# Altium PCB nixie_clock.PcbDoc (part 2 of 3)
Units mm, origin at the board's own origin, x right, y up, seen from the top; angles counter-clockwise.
Board outline 295 x 120 mm, 2 copper layers (Top Layer, Bottom Layer), stack 0.325 mm thick; 320 components, 396 nets, 1330 pads, 452 vias.
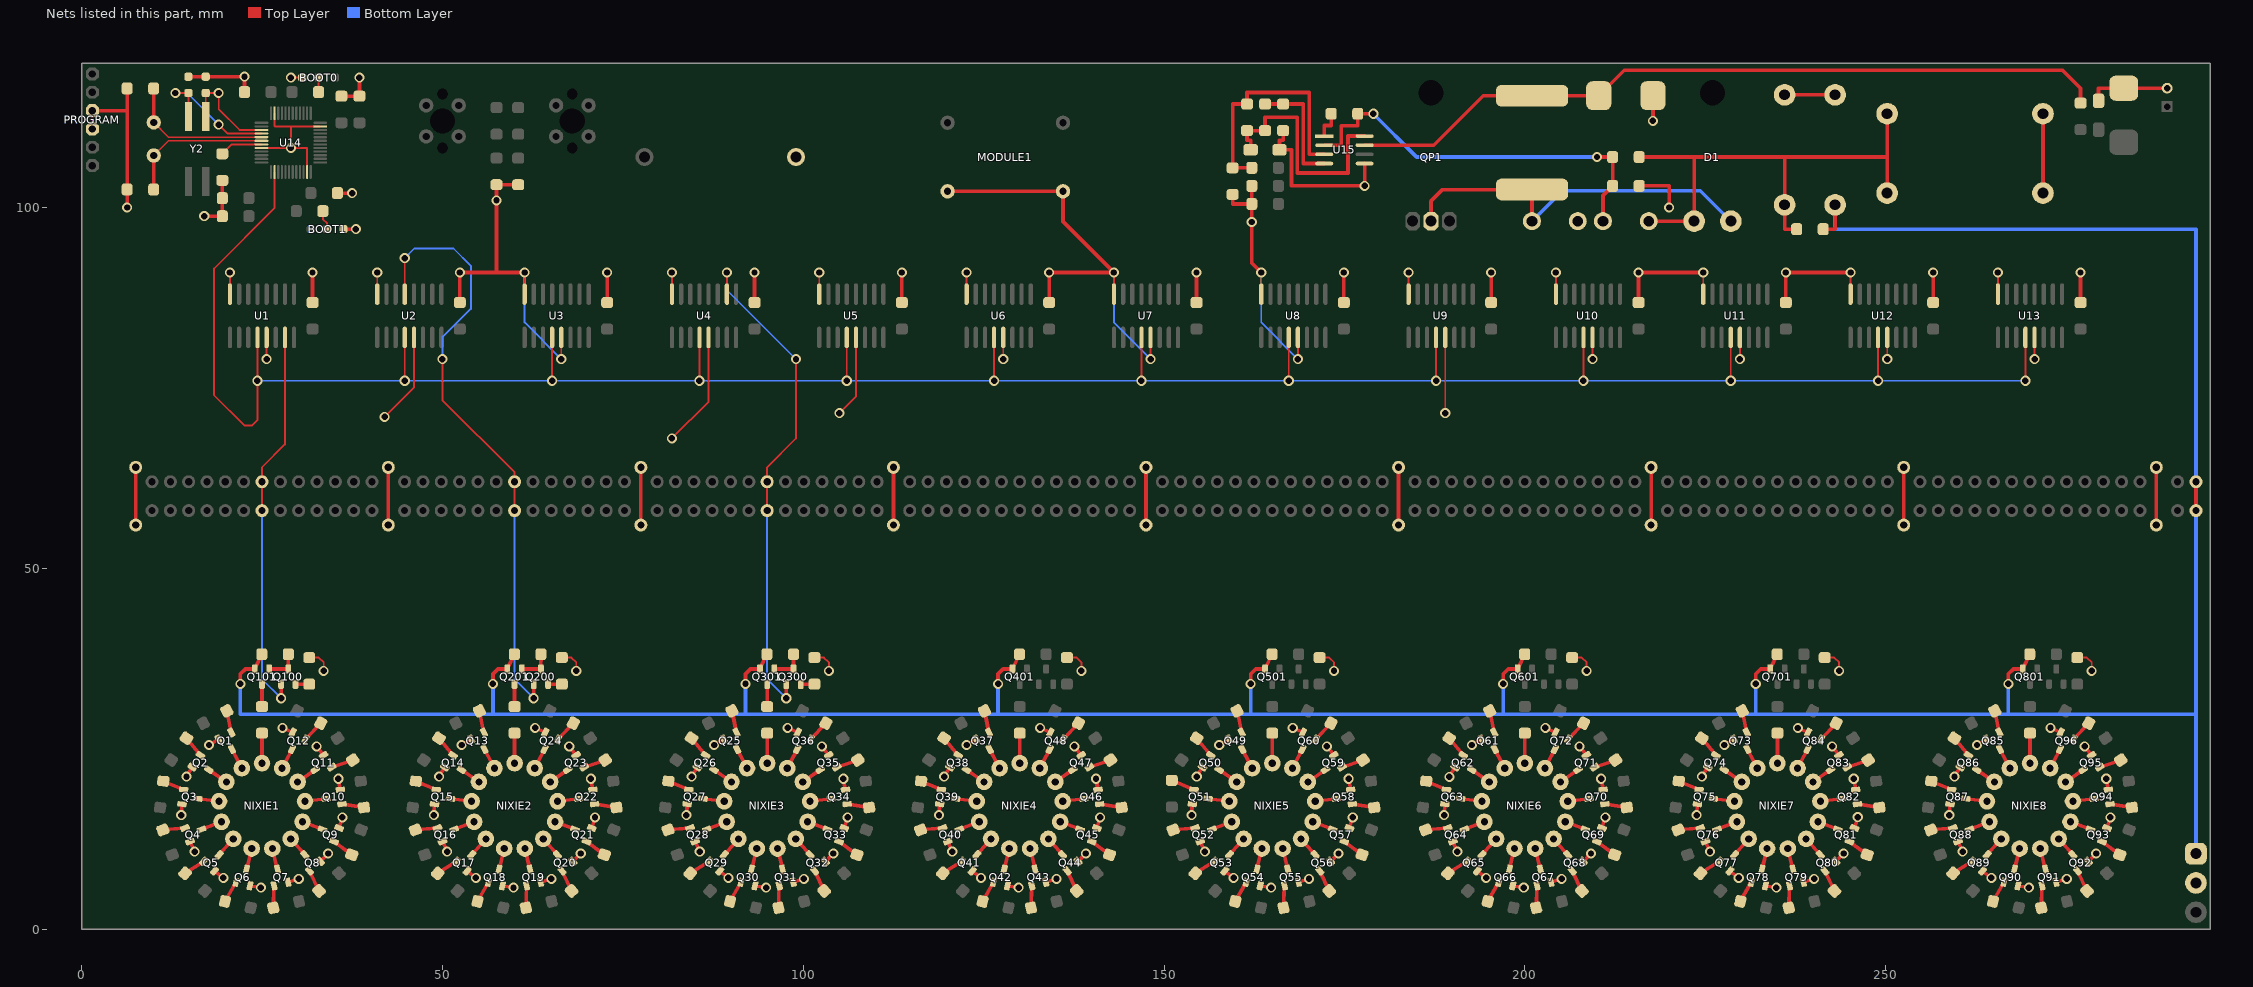
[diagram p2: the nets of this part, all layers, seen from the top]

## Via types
v1: diameter 1.397, hole 0.889, Top Layer to Bottom Layer, 452 vias

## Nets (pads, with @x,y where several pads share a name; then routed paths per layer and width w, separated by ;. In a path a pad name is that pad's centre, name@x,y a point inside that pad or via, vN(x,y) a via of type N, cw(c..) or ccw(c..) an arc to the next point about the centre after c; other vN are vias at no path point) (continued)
GND: BOOT0.3 BOOT1.3 C1.1 C2.1 C3.1 C4.1 C5.1 C6.1 C7.1 C8.1 C9.1 C10.1 C11.1 C12.1 C13.1 C14.1 C15.1 C16.1 C17.1 C18.1 C19.1 C20.1 C21.1 C22.1 C23.1 C24.1 CoinCell.1 CP1.2 CP2.2 CP3.2 CP7.2 CP9.2 CP10.2 CP11.2 CP12.2 CP15.2 CP16.2 CP18.2 MODULE1.1 MODULE1.4 P1.2 pad.802 pad.807 pad.808 pad.809 pad.810 pad.811 pad.812 pad.813 pad.814 pad.815 pad.816 pad.817 pad.818 pad.819 pad.820 pad.825 pad.826 pad.827 pad.828 PROGRAM.3 PROGRAM.4 Q1.2 Q2.2 Q3.2 Q4.2 Q5.2 Q6.2 Q7.2 Q8.2 Q9.2 Q10.2 Q11.2 Q12.2 Q13.2 Q14.2 Q15.2 Q16.2 Q17.2 Q18.2 Q19.2 Q20.2 Q21.2 Q22.2 Q23.2 Q24.2 Q25.2 Q26.2 Q27.2 Q28.2 Q29.2 Q30.2 Q31.2 Q32.2 Q33.2 Q34.2 Q35.2 Q36.2 Q37.2 Q38.2 Q39.2 Q40.2 Q41.2 Q42.2 Q43.2 Q44.2 Q45.2 Q46.2 Q47.2 Q48.2 Q49.2 Q50.2 Q51.2 Q52.2 Q53.2 Q54.2 Q55.2 Q56.2 Q57.2 Q58.2 Q59.2 Q60.2 Q61.2 Q62.2 Q63.2 Q64.2 Q65.2 Q66.2 Q67.2 Q68.2 Q69.2 Q70.2 Q71.2 Q72.2 Q73.2 Q74.2 Q75.2 Q76.2 Q77.2 Q78.2 Q79.2 Q80.2 Q81.2 Q82.2 Q83.2 Q84.2 Q85.2 Q86.2 Q87.2 Q88.2 Q89.2 Q90.2 Q91.2 Q92.2 Q93.2 Q94.2 Q95.2 Q96.2 R100.2 R111.1 R112.1 R200.2 R300.2 R400.2 R500.2 R600.2 R700.2 R800.2 RP10.2 RP11.2 RP16.2 U1.8 U1.13 U2.8 U2.13 U3.8 U3.13 U4.8 U4.13 U5.8 U5.13 U6.8 U6.13 U7.8 U7.13 U8.8 U8.13 U9.8 U9.13 U10.8 U10.13 U11.8 U11.13 U12.8 U12.13 U13.8 U13.13 U14.8 U14.23 U14.35 U14.47 U15.5 | length 694.6
  Top Layer w0.254: U1.8@20.555,88 v1(20.555,91) ; U14.8@24.925,108.25 v1(29,108.25) ; v1(25.635,79) U1.13@25.635,82 ; U14.47@26.75,113.075 26.75,111.3 26.81,111.24 29,111.24 ; v1(29,118) BOOT0.3@30.58,118 ; U14.23@31.25,104.925 31.25,108.25 v1(29,108.25) ; R100.2@31.55,37.637 32.873,37.637 33.55,36.96 v1(33.55,35.795) ; U14.35@33.075,111.25 29.01,111.25 29,111.24 ; U2.8@40.972,88 v1(40.972,91) ; v1(42,71) 46.052,75.052 U2.13@46.052,82 ; U3.8@61.388,88 v1(61.388,91) ; v1(66.468,79) U3.13@66.468,82 ; R200.2@66.55,37.637 67.873,37.637 68.55,36.96 v1(68.55,35.795) ; v1(81.805,68) 86.885,73.08 U4.13@86.885,82 ; U4.8@81.805,88 v1(81.805,91) ; R300.2@101.55,37.637 102.873,37.637 103.55,36.96 v1(103.55,35.795) ; U5.8@102.222,88 v1(102.222,91) ; v1(105,71.5) 107.302,73.802 U5.13@107.302,82 ; U6.8@122.638,88 v1(122.638,91) ; v1(127.718,79) U6.13@127.718,82 ; R400.2@136.55,37.637 137.873,37.637 138.55,36.96 v1(138.55,35.795) ; U7.8@143.055,88 v1(143.055,91) ; v1(148.135,79) U7.13@148.135,82 ; U8.8@163.472,88 v1(163.472,91) ; v1(168.552,79) U8.13@168.552,82 ; R500.2@171.55,37.637 172.873,37.637 173.55,36.96 v1(173.55,35.795) ; U9.8@183.888,88 v1(183.888,91) ; v1(188.968,71.5) U9.13@188.968,82 ; U10.8@204.305,88 v1(204.305,91) ; R600.2@206.55,37.637 207.873,37.637 208.55,36.96 v1(208.55,35.795) ; v1(209.385,79) U10.13@209.385,82 ; U11.8@224.722,88 v1(224.722,91) ; v1(229.802,79) U11.13@229.802,82 ; R700.2@241.55,37.637 242.873,37.637 243.55,36.96 v1(243.55,35.795) ; U12.8@245.138,88 v1(245.138,91) ; v1(250.218,79) U12.13@250.218,82 ; U13.8@265.555,88 v1(265.555,91) ; v1(270.635,79) U13.13@270.635,82 ; R800.2@276.55,37.637 277.873,37.637 278.55,36.96 v1(278.55,35.795) ; v1(29,108.25) 29,111.24
  Top Layer w0.508: PROGRAM.4@1.49,110.89 PROGRAM.3@1.49,113.43 6.189,113.43 6.309,113.31 ; C15.1@6.309,102.5 6.309,113.31 ; C14.1@6.309,116.5 6.309,113.31 ; v1(6.309,100) C15.1@6.309,102.5 ; pad.827@7.5,56 pad.828@7.5,64 ; v1(13.815,15.794) Q3.2@13.91,17.339 ; v1(14.536,21.13) Q2.2@15.338,22.454 ; C17.1@14.8,118.13 C16.1@17.2,118.13 v1(22.569,118.13) C21.1@22.569,116 ; Q4.2@15.023,12.147 v1(15.656,10.734) ; v1(17,98.8) C23.1@19.499,98.8 C24.1@19.499,101.3 19.5,101.301 C18.1@19.5,103.759 ; v1(17.654,25.52) Q1.2@18.979,26.32 ; Q5.2@18.421,8.066 v1(19.638,7.11) ; Q6.2@23.326,6.032 v1(24.848,5.751) ; v1(27.839,27.886) Q12.2@29.25,27.249 ; Q7.2@28.615,6.51 v1(30.093,6.969) ; C1.1@32,86.842 v1(32,91) ; v1(32.573,25.32) Q11.2@33.526,24.1 ; Q8.2@33.076,9.392 v1(34.172,10.485) ; C19.1@35.441,102 v1(37.5,102) ; v1(35.572,20.848) Q10.2@35.849,19.324 ; Q9.2@35.686,14.016 v1(36.149,15.493) ; C20.1@36,115.431 C22.1@38.5,115.431 v1(38.5,118) ; BOOT1.3@36.28,97 v1(38,97) ; pad.820@42.5,56 pad.807@42.5,64 ; v1(48.815,15.794) Q15.2@48.91,17.339 ; v1(49.536,21.13) Q14.2@50.338,22.454 ; Q16.2@50.023,12.147 v1(50.656,10.734) ; C2.1@52.417,86.842 v1(52.417,91) 57.33,91 ; v1(52.654,25.52) Q13.2@53.979,26.32 ; Q17.2@53.421,8.066 v1(54.638,7.11) ; Q18.2@58.326,6.032 v1(59.848,5.751) ; R111.1@60.5,103.159 R112.1@57.5,103.159 v1(57.5,101) 57.5,91.17 57.33,91 ; v1(61.388,91) 57.33,91 ; v1(62.839,27.886) Q24.2@64.25,27.249 ; Q19.2@63.615,6.51 v1(65.093,6.969) ; v1(67.573,25.32) Q23.2@68.526,24.1 ; Q20.2@68.076,9.392 v1(69.172,10.485) ; v1(70.572,20.848) Q22.2@70.849,19.324 ; Q21.2@70.686,14.016 v1(71.149,15.493) ; C3.1@72.833,86.842 v1(72.833,91) ; pad.819@77.5,56 pad.809@77.5,64 ; v1(83.815,15.794) Q27.2@83.91,17.339 ; v1(84.536,21.13) Q26.2@85.338,22.454 ; Q28.2@85.023,12.147 v1(85.656,10.734) ; v1(87.654,25.52) Q25.2@88.979,26.32 ; Q29.2@88.421,8.066 v1(89.638,7.11) ; C4.1@93.25,86.842 v1(93.25,91) ; Q30.2@93.326,6.032 v1(94.848,5.751) ; v1(97.839,27.886) Q36.2@99.25,27.249 ; Q31.2@98.615,6.51 v1(100.093,6.969) ; v1(102.573,25.32) Q35.2@103.526,24.1 ; Q32.2@103.076,9.392 v1(104.172,10.485) ; v1(105.572,20.848) Q34.2@105.849,19.324 ; Q33.2@105.686,14.016 v1(106.149,15.493) ; pad.818@112.5,56 pad.810@112.5,64 ; C5.1@113.667,86.842 v1(113.667,91) ; v1(118.815,15.794) Q39.2@118.91,17.339 ; v1(119.536,21.13) Q38.2@120.338,22.454 ; MODULE1.4@120,102.25 MODULE1.1@136,102.25 136,98.055 v1(143.055,91) v1(134.083,91) C6.1@134.083,86.842 ; Q40.2@120.023,12.147 v1(120.656,10.734) ; v1(122.654,25.52) Q37.2@123.979,26.32 ; Q41.2@123.421,8.066 v1(124.638,7.11) ; Q42.2@128.326,6.032 v1(129.848,5.751) ; v1(132.839,27.886) Q48.2@134.25,27.249 ; Q43.2@133.615,6.51 v1(135.093,6.969) ; v1(137.573,25.32) Q47.2@138.526,24.1 ; Q44.2@138.076,9.392 v1(139.172,10.485) ; v1(140.572,20.848) Q46.2@140.849,19.324 ; Q45.2@140.686,14.016 v1(141.149,15.493) ; pad.817@147.5,56 pad.811@147.5,64 ; v1(153.815,15.794) Q51.2@153.91,17.339 ; C7.1@154.5,86.842 v1(154.5,91) ; v1(154.536,21.13) Q50.2@155.338,22.454 ; Q52.2@155.023,12.147 v1(155.656,10.734) ; v1(157.654,25.52) Q49.2@158.979,26.32 ; Q53.2@158.421,8.066 v1(159.638,7.11) ; CP11.2@159.5,101.819 159.5,100.5 RP11.2@162.159,100.5 ; RP10.2@162.159,103 RP11.2@162.159,100.5 ; Q54.2@163.326,6.032 v1(164.848,5.751) ; v1(163.472,91) 162.159,92.313 v1(162.159,98) RP11.2@162.159,100.5 ; CP7.2@166.5,110.659 166.5,109.33 166,109.33 CP10.2@166,108 167.67,108 167.67,103 v1(177.8,103) U15.5@177.8,106.095 ; v1(167.839,27.886) Q60.2@169.25,27.249 ; Q55.2@168.615,6.51 v1(170.093,6.969) ; v1(172.573,25.32) Q59.2@173.526,24.1 ; Q56.2@173.076,9.392 v1(174.172,10.485) ; C8.1@174.917,86.842 v1(174.917,91) ; v1(175.572,20.848) Q58.2@175.849,19.324 ; Q57.2@175.686,14.016 v1(176.149,15.493) ; pad.816@182.5,56 pad.812@182.5,64 ; v1(188.815,15.794) Q63.2@188.91,17.339 ; v1(189.53,21.11) Q62.2@190.338,22.454 ; Q64.2@190.023,12.147 v1(190.656,10.734) ; v1(192.654,25.52) Q61.2@193.979,26.32 ; Q65.2@193.421,8.066 v1(194.638,7.11) ; C9.1@195.333,86.842 v1(195.333,91) ; Q66.2@198.326,6.032 v1(199.848,5.751) ; v1(202.839,27.886) Q72.2@204.25,27.249 ; Q67.2@203.615,6.51 v1(205.093,6.969) ; v1(207.573,25.32) Q71.2@208.526,24.1 ; Q68.2@208.076,9.392 v1(209.172,10.485) ; v1(210.572,20.848) Q70.2@210.849,19.324 ; Q69.2@210.686,14.016 v1(211.149,15.493) ; C10.1@215.75,86.842 v1(215.75,91) v1(224.722,91) ; RP16.2@215.842,103 220,103 v1(220,100) ; pad.815@217.5,56 pad.813@217.5,64 ; v1(217.75,112) CP9.2@217.75,115.5 ; v1(223.815,15.794) Q75.2@223.91,17.339 ; v1(224.536,21.13) Q74.2@225.338,22.454 ; Q76.2@225.023,12.147 v1(225.656,10.734) ; v1(227.654,25.52) Q73.2@228.979,26.32 ; Q77.2@228.421,8.066 v1(229.638,7.11) ; Q78.2@233.326,6.032 v1(234.848,5.751) ; CP12.2@236,115.62 CP3.2@243,115.62 ; C11.1@236.167,86.842 v1(236.167,91) v1(245.138,91) ; v1(237.83,27.88) Q84.2@239.25,27.249 ; Q79.2@238.615,6.51 v1(240.093,6.969) ; v1(242.573,25.32) Q83.2@243.526,24.1 ; Q80.2@243.076,9.392 v1(244.172,10.485) ; v1(245.572,20.848) Q82.2@245.849,19.324 ; Q81.2@245.686,14.016 v1(246.13,15.52) ; pad.814@252.5,56 pad.808@252.5,64 ; C12.1@256.583,86.842 v1(256.583,91) ; v1(258.815,15.794) Q87.2@258.91,17.339 ; v1(259.536,21.13) Q86.2@260.338,22.454 ; Q88.2@260.023,12.147 v1(260.656,10.734) ; v1(262.654,25.52) Q85.2@263.979,26.32 ; Q89.2@263.421,8.066 v1(264.638,7.11) ; Q90.2@268.326,6.032 v1(269.848,5.751) ; CP2.2@271.795,102 CP1.2@271.795,113 ; v1(272.839,27.886) Q96.2@274.25,27.249 ; Q91.2@273.615,6.51 v1(275.093,6.969) ; C13.1@277,86.842 v1(277,91) ; v1(277.573,25.32) Q95.2@278.526,24.1 ; Q92.2@278.076,9.392 v1(279.172,10.485) ; CP18.2@279.5,114.79 279.5,116.54 CP16.2@283,116.54 P1.2@289,116.54 ; v1(280.572,20.848) Q94.2@280.849,19.324 ; Q93.2@280.686,14.016 v1(281.149,15.493) ; pad.825@287.5,56 pad.826@287.5,64
  Bottom Layer w0.254: v1(61.388,91) 61.388,84.08 v1(66.468,79) ; v1(143.055,91) 143.055,84.08 v1(148.135,79) ; v1(163.472,91) 163.472,84.08 v1(168.552,79)
HV: CP3.1 L2.1 pad.803 pad.823 pad.824 Q101.2 Q201.2 Q301.2 Q401.2 Q501.2 Q601.2 Q701.2 Q801.2 R102.1 R202.1 R302.1 R402.1 R502.1 R602.1 R702.1 R802.1 | length 500.9
  Top Layer w0.508: v1(22,34) 22,35.35 22.7,36.05 Q101.2@24,36.05 R102.1@24.968,38.1 ; v1(57,34) 57,35.35 57.7,36.05 Q201.2@59,36.05 R202.1@59.969,38.1 ; v1(92,34) 92,35.35 92.7,36.05 Q301.2@94,36.05 R302.1@94.968,38.1 ; v1(127,34) 127,35.35 127.7,36.05 Q401.2@129,36.05 R402.1@129.969,38.1 ; v1(162,34) 162,35.35 162.7,36.05 Q501.2@164,36.05 R502.1@164.968,38.1 ; v1(197,34) 197,35.35 197.7,36.05 Q601.2@199,36.05 R602.1@199.969,38.1 ; v1(232,34) 232,35.35 232.7,36.05 Q701.2@234,36.05 R702.1@234.968,38.1 ; L2.1@241.342,97 243,97 CP3.1@243,100.38 ; v1(267,34) 267,35.35 267.7,36.05 Q801.2@269,36.05 R802.1@269.968,38.1 ; pad.824@293,58 pad.823@293,62
  Bottom Layer w0.508: v1(22,34) 22,29.77 231.96,29.77 ; 57,29.81 v1(57,34) ; 92,29.81 v1(92,34) ; 127,29.81 v1(127,34) ; 162,29.81 v1(162,34) ; 197,29.81 v1(197,34) ; v1(232,34) 232,29.81 231.96,29.77 ; CP3.1@243,100.38 243,97.01 293,97.01 pad.823@293,62 pad.824@293,58 293,29.77 ; v1(267,34) 267,29.77 ; pad.803@293,10.47 293,29.77 ; 231.96,29.77 267,29.77 ; 267,29.77 293,29.77
LATCH: U1.12 U2.12 U3.12 U4.12 U5.12 U6.12 U7.12 U8.12 U9.12 U10.12 U11.12 U12.12 U13.12 U14.14 | length 370.9
  Top Layer w0.254: U1.12@24.365,82 v1(24.365,76) 24.365,70.525 23.65,69.81 22.55,69.81 18.35,74.01 18.35,91.54 26.75,99.94 U14.14@26.75,104.925 ; v1(44.782,76) U2.12@44.782,82 ; v1(65.198,76) U3.12@65.198,82 ; v1(85.615,76) U4.12@85.615,82 ; v1(106.032,76) U5.12@106.032,82 ; v1(126.448,76) U6.12@126.448,82 ; v1(146.865,76) U7.12@146.865,82 ; v1(167.282,76) U8.12@167.282,82 ; v1(187.698,76) U9.12@187.698,82 ; v1(208.115,76) U10.12@208.115,82 ; v1(228.532,76) U11.12@228.532,82 ; v1(248.948,76) U12.12@248.948,82 ; v1(269.365,76) U13.12@269.365,82
  Bottom Layer w0.254: v1(24.365,76) v1(44.782,76) v1(65.198,76) v1(85.615,76) v1(106.032,76) v1(126.448,76) v1(146.865,76) v1(167.282,76) v1(187.698,76) v1(208.115,76) v1(228.532,76) v1(248.948,76) v1(269.365,76)
NetBOOT0_2: BOOT0.2 R109.1 | length 2
  Top Layer w0.254: BOOT0.2@32.84,118 32.841,117.999 R109.1@32.841,116
NetBOOT1_2: BOOT1.2 R110.2 | length 2.7
  Top Layer w0.254: R110.2@33.432,99.5 33.432,98.399 34.02,97.81 BOOT1.2@34.02,97
NetC14_2: C14.2 U14.5 Y1.2 | length 20.5
  Top Layer w0.254: C14.2@9.991,116.5 C14.2@10,116.491 ; Y1.2@10,111.793 12.043,109.75 U14.5@24.925,109.75
  Top Layer w0.508: Y1.2@10,111.793 C14.2@10,116.491
NetC15_2: C15.2 U14.6 Y1.1 | length 20.5
  Top Layer w0.254: C15.2@9.991,102.5 C15.2@10,102.509 ; Y1.1@10,107.207 12.043,109.25 U14.6@24.925,109.25
  Top Layer w0.508: C15.2@10,102.509 Y1.1@10,107.207
NetC16_2: C16.2 U14.3 Y2.1 | length 14.4
  Top Layer w0.254: Y2.1@17.2,112.62 C16.2@17.2,115.87 v1(19,115.87) 19,113.63 21.88,110.75 U14.3@24.925,110.75
NetC17_2: C17.2 U14.4 Y2.2 | length 19.3
  Top Layer w0.254: v1(13,115.87) C17.2@14.8,115.87 Y2.2@14.8,112.62 ; v1(19,111.5) 20.25,110.25 U14.4@24.925,110.25
  Bottom Layer w0.254: v1(13,115.87) 14.63,115.87 v1(19,111.5)
NetC18_2: C18.2 U14.7 | length 6
  Top Layer w0.254: C18.2@19.5,107.441 20.809,108.75 U14.7@24.925,108.75
NetCP1_1: CP1.1 CP2.1 CP6.1 CP12.1 D1.2 L2.2 RP15.1 | length 72.3
  Top Layer w0.508: RP15.1@215.842,107 223.46,107 ; CP6.1@217.175,98.11 D1.2@223.46,98.11 223.46,107 ; L2.2@237.659,97 236,97 CP12.1@236,100.38 236,106.85 235.85,107 ; CP2.1@250.205,102 250.205,107.16 ; CP1.1@250.205,113 250.205,107.16 ; 223.46,107 235.85,107 ; 235.85,107 250.045,107 250.205,107.16
NetCP5_1: CP5.1 U15.1 | length 4.1
  Top Layer w0.508: U15.1@172.2,109.905 172.2,111.37 173.159,111.37 CP5.1@173.159,113
NetCP5_2: CP5.2 CP6.2 RP15.2 RP16.1 U15.2 | length 56.3
  Top Layer w0.508: U15.2@172.2,108.635 174.55,108.635 174.55,111.34 176.842,111.34 CP5.2@176.842,113 v1(179,113) ; v1(210,107) RP15.2@212.159,107 RP16.1@212.159,103 210.825,101.666 CP6.2@210.825,98.11
  Bottom Layer w0.508: v1(179,113) 185,107 v1(210,107)
NetCP7_1: CP7.1 RP2.2 U15.4 | length 16.4
  Top Layer w0.508: RP2.2@164,114.342 CP7.1@166.5,114.342 169.29,114.342 169.29,106.095 U15.4@172.2,106.095
NetCP9_1: CP9.1 L1.1 L3.2 U15.7 | length 106.6
  Top Layer w0.508: U15.7@177.8,108.635 187.375,108.635 194.24,115.5 L3.2@201,115.5 CP9.1@210.25,115.5 213.77,119.02 274.5,119.02 277,116.52 L1.1@277,114.472
NetCP10_1: CP10.1 RP2.1 RP12.1 U15.8 | length 34.1
  Top Layer w0.508: CP10.1@162,108 162,109.31 161.5,109.31 RP12.1@161.5,110.659 RP2.1@164,110.659 164,112.5 168.45,112.5 168.45,104.78 175.5,104.78 175.5,109.905 U15.8@177.8,109.905
NetCP11_1: CP11.1 RP8.1 RP12.2 U15.3 | length 34.4
  Top Layer w0.508: RP8.1@162.159,105.5 159.502,105.5 CP11.1@159.5,105.502 159.5,114.342 RP12.2@161.5,114.342 161.5,115.94 170.13,115.94 170.13,107.365 U15.3@172.2,107.365
NetCP15_1: CP15.1 D1.1 L3.1 QP1.2 | length 52.9
  Top Layer w0.508: QP1.2@187,98.11 187,100.89 188.595,102.485 200.985,102.485 CP15.1@200.985,98.11
  Bottom Layer w0.508: CP15.1@200.985,98.11 205.215,102.34 224.31,102.34 D1.1@228.54,98.11
NetNIXIE1_0: NIXIE1.0 Q11.3 | length 3
  Top Layer w0.508: NIXIE1.0@29.938,20.408 Q11.3@32.366,22.084
NetNIXIE1_1: NIXIE1.1 Q2.3 | length 3
  Top Layer w0.508: Q2.3@17.634,22.084 NIXIE1.1@20.062,20.408
NetNIXIE1_2: NIXIE1.2 Q3.3 | length 3
  Top Layer w0.508: Q3.3@16.115,18.079 NIXIE1.2@19.044,17.723
NetNIXIE1_3: NIXIE1.3 Q4.3 | length 3
  Top Layer w0.508: Q4.3@16.632,13.826 NIXIE1.3@19.39,14.872
NetNIXIE1_4: NIXIE1.4 Q5.3 | length 3
  Top Layer w0.508: Q5.3@19.065,10.301 NIXIE1.4@21.021,12.509
NetNIXIE1_5: NIXIE1.5 Q6.3 | length 3
  Top Layer w0.508: Q6.3@22.858,8.31 NIXIE1.5@23.564,11.174
NetNIXIE1_6: NIXIE1.6 Q7.3 | length 3
  Top Layer w0.508: NIXIE1.6@26.436,11.174 Q7.3@27.142,8.31
NetNIXIE1_7: NIXIE1.7 Q8.3 | length 3
  Top Layer w0.508: NIXIE1.7@28.979,12.509 Q8.3@30.935,10.301
NetNIXIE1_8: NIXIE1.8 Q9.3 | length 3
  Top Layer w0.508: NIXIE1.8@30.61,14.872 Q9.3@33.368,13.826
NetNIXIE1_9: NIXIE1.9 Q10.3 | length 3
  Top Layer w0.508: NIXIE1.9@30.956,17.723 Q10.3@33.885,18.078
NetNIXIE1_A: NIXIE1.A R101.2 | length 4.2
  Top Layer w0.508: NIXIE1.A@25,23 R101.2@25,27.159
NetNIXIE1_LP: NIXIE1.LP Q1.3 | length 3
  Top Layer w0.508: Q1.3@20.841,24.925 NIXIE1.LP@22.212,22.313
NetNIXIE1_RP: NIXIE1.RP Q12.3 | length 3
  Top Layer w0.508: NIXIE1.RP@27.789,22.313 Q12.3@29.16,24.925
NetNIXIE2_0: NIXIE2.0 Q23.3 | length 2.9
  Top Layer w0.508: NIXIE2.0@64.938,20.408 Q23.3@67.366,22.084
NetNIXIE2_1: NIXIE2.1 Q14.3 | length 3
  Top Layer w0.508: Q14.3@52.634,22.084 NIXIE2.1@55.062,20.408
NetNIXIE2_2: NIXIE2.2 Q15.3 | length 2.9
  Top Layer w0.508: Q15.3@51.115,18.079 NIXIE2.2@54.044,17.723
NetNIXIE2_3: NIXIE2.3 Q16.3 | length 3
  Top Layer w0.508: Q16.3@51.632,13.826 NIXIE2.3@54.39,14.872
NetNIXIE2_4: NIXIE2.4 Q17.3 | length 3
  Top Layer w0.508: Q17.3@54.065,10.301 NIXIE2.4@56.021,12.509
NetNIXIE2_5: NIXIE2.5 Q18.3 | length 3
  Top Layer w0.508: Q18.3@57.858,8.31 NIXIE2.5@58.564,11.174
NetNIXIE2_6: NIXIE2.6 Q19.3 | length 3
  Top Layer w0.508: NIXIE2.6@61.436,11.174 Q19.3@62.142,8.31
NetNIXIE2_7: NIXIE2.7 Q20.3 | length 3
  Top Layer w0.508: NIXIE2.7@63.979,12.509 Q20.3@65.935,10.301
NetNIXIE2_8: NIXIE2.8 Q21.3 | length 3
  Top Layer w0.508: NIXIE2.8@65.61,14.872 Q21.3@68.368,13.826
NetNIXIE2_9: NIXIE2.9 Q22.3 | length 3
  Top Layer w0.508: NIXIE2.9@65.956,17.723 Q22.3@68.885,18.078
NetNIXIE2_A: NIXIE2.A R201.2 | length 4.2
  Top Layer w0.508: NIXIE2.A@60,23 R201.2@60,27.159
NetNIXIE2_LP: NIXIE2.LP Q13.3 | length 2.9
  Top Layer w0.508: Q13.3@55.841,24.925 NIXIE2.LP@57.212,22.313
NetNIXIE2_RP: NIXIE2.RP Q24.3 | length 2.9
  Top Layer w0.508: NIXIE2.RP@62.789,22.313 Q24.3@64.16,24.925
NetNIXIE3_0: NIXIE3.0 Q35.3 | length 3
  Top Layer w0.508: NIXIE3.0@99.938,20.408 Q35.3@102.366,22.084
NetNIXIE3_1: NIXIE3.1 Q26.3 | length 3
  Top Layer w0.508: Q26.3@87.634,22.084 NIXIE3.1@90.062,20.408
NetNIXIE3_2: NIXIE3.2 Q27.3 | length 3
  Top Layer w0.508: Q27.3@86.115,18.079 NIXIE3.2@89.044,17.723
NetNIXIE3_3: NIXIE3.3 Q28.3 | length 3
  Top Layer w0.508: Q28.3@86.632,13.826 NIXIE3.3@89.39,14.872
NetNIXIE3_4: NIXIE3.4 Q29.3 | length 3
  Top Layer w0.508: Q29.3@89.065,10.301 NIXIE3.4@91.021,12.509
NetNIXIE3_5: NIXIE3.5 Q30.3 | length 3
  Top Layer w0.508: Q30.3@92.858,8.31 NIXIE3.5@93.564,11.174
NetNIXIE3_6: NIXIE3.6 Q31.3 | length 3
  Top Layer w0.508: NIXIE3.6@96.436,11.174 Q31.3@97.142,8.31
NetNIXIE3_7: NIXIE3.7 Q32.3 | length 3
  Top Layer w0.508: NIXIE3.7@98.979,12.509 Q32.3@100.935,10.301
NetNIXIE3_8: NIXIE3.8 Q33.3 | length 3
  Top Layer w0.508: NIXIE3.8@100.61,14.872 Q33.3@103.368,13.826
NetNIXIE3_9: NIXIE3.9 Q34.3 | length 3
  Top Layer w0.508: NIXIE3.9@100.956,17.723 Q34.3@103.885,18.078
NetNIXIE3_A: NIXIE3.A R301.2 | length 4.2
  Top Layer w0.508: NIXIE3.A@95,23 R301.2@95,27.159
NetNIXIE3_LP: NIXIE3.LP Q25.3 | length 3
  Top Layer w0.508: Q25.3@90.841,24.925 NIXIE3.LP@92.212,22.313
NetNIXIE3_RP: NIXIE3.RP Q36.3 | length 3
  Top Layer w0.508: NIXIE3.RP@97.789,22.313 Q36.3@99.16,24.925
NetNIXIE4_0: NIXIE4.0 Q47.3 | length 3
  Top Layer w0.508: NIXIE4.0@134.938,20.408 Q47.3@137.366,22.084
NetNIXIE4_1: NIXIE4.1 Q38.3 | length 3
  Top Layer w0.508: Q38.3@122.634,22.084 NIXIE4.1@125.062,20.408
NetNIXIE4_2: NIXIE4.2 Q39.3 | length 3
  Top Layer w0.508: Q39.3@121.115,18.079 NIXIE4.2@124.044,17.723
NetNIXIE4_3: NIXIE4.3 Q40.3 | length 3
  Top Layer w0.508: Q40.3@121.632,13.826 NIXIE4.3@124.39,14.872
NetNIXIE4_4: NIXIE4.4 Q41.3 | length 3
  Top Layer w0.508: Q41.3@124.065,10.301 NIXIE4.4@126.021,12.509
NetNIXIE4_5: NIXIE4.5 Q42.3 | length 2.9
  Top Layer w0.508: Q42.3@127.858,8.31 NIXIE4.5@128.564,11.174
NetNIXIE4_6: NIXIE4.6 Q43.3 | length 3
  Top Layer w0.508: NIXIE4.6@131.436,11.174 Q43.3@132.142,8.31
NetNIXIE4_7: NIXIE4.7 Q44.3 | length 3
  Top Layer w0.508: NIXIE4.7@133.979,12.509 Q44.3@135.935,10.301
NetNIXIE4_8: NIXIE4.8 Q45.3 | length 3
  Top Layer w0.508: NIXIE4.8@135.61,14.872 Q45.3@138.368,13.826
NetNIXIE4_9: NIXIE4.9 Q46.3 | length 3
  Top Layer w0.508: NIXIE4.9@135.956,17.723 Q46.3@138.885,18.078
NetNIXIE4_A: NIXIE4.A R401.2 | length 4.2
  Top Layer w0.508: NIXIE4.A@130,23 R401.2@130,27.159
NetNIXIE4_LP: NIXIE4.LP Q37.3 | length 3
  Top Layer w0.508: Q37.3@125.841,24.925 NIXIE4.LP@127.212,22.313
NetNIXIE4_RP: NIXIE4.RP Q48.3 | length 3
  Top Layer w0.508: NIXIE4.RP@132.789,22.313 Q48.3@134.16,24.925
NetNIXIE5_0: NIXIE5.0 Q59.3 | length 3
  Top Layer w0.508: NIXIE5.0@169.938,20.408 Q59.3@172.366,22.084
NetNIXIE5_1: NIXIE5.1 Q50.3 | length 3
  Top Layer w0.508: Q50.3@157.634,22.084 NIXIE5.1@160.062,20.408
NetNIXIE5_2: NIXIE5.2 Q51.3 | length 3
  Top Layer w0.508: Q51.3@156.115,18.079 NIXIE5.2@159.044,17.723
NetNIXIE5_3: NIXIE5.3 Q52.3 | length 3
  Top Layer w0.508: Q52.3@156.632,13.826 NIXIE5.3@159.39,14.872
NetNIXIE5_4: NIXIE5.4 Q53.3 | length 3
  Top Layer w0.508: Q53.3@159.065,10.301 NIXIE5.4@161.021,12.509
NetNIXIE5_5: NIXIE5.5 Q54.3 | length 3
  Top Layer w0.508: Q54.3@162.858,8.31 NIXIE5.5@163.564,11.174
NetNIXIE5_6: NIXIE5.6 Q55.3 | length 3
  Top Layer w0.508: NIXIE5.6@166.436,11.174 Q55.3@167.142,8.31
NetNIXIE5_7: NIXIE5.7 Q56.3 | length 3
  Top Layer w0.508: NIXIE5.7@168.979,12.509 Q56.3@170.935,10.301
NetNIXIE5_8: NIXIE5.8 Q57.3 | length 3
  Top Layer w0.508: NIXIE5.8@170.61,14.872 Q57.3@173.368,13.826
NetNIXIE5_9: NIXIE5.9 Q58.3 | length 3
  Top Layer w0.508: NIXIE5.9@170.956,17.723 Q58.3@173.885,18.078
NetNIXIE5_A: NIXIE5.A R501.2 | length 4.2
  Top Layer w0.508: NIXIE5.A@165,23 R501.2@165,27.159
NetNIXIE5_LP: NIXIE5.LP Q49.3 | length 3
  Top Layer w0.508: Q49.3@160.841,24.925 NIXIE5.LP@162.212,22.313
NetNIXIE5_RP: NIXIE5.RP Q60.3 | length 3
  Top Layer w0.508: NIXIE5.RP@167.789,22.313 Q60.3@169.16,24.925
NetNIXIE6_0: NIXIE6.0 Q71.3 | length 2.9
  Top Layer w0.508: NIXIE6.0@204.938,20.408 Q71.3@207.366,22.084
NetNIXIE6_1: NIXIE6.1 Q62.3 | length 3
  Top Layer w0.508: Q62.3@192.634,22.084 NIXIE6.1@195.062,20.408
NetNIXIE6_2: NIXIE6.2 Q63.3 | length 3
  Top Layer w0.508: Q63.3@191.115,18.079 NIXIE6.2@194.044,17.723
NetNIXIE6_3: NIXIE6.3 Q64.3 | length 3
  Top Layer w0.508: Q64.3@191.632,13.826 NIXIE6.3@194.39,14.872
NetNIXIE6_4: NIXIE6.4 Q65.3 | length 3
  Top Layer w0.508: Q65.3@194.065,10.301 NIXIE6.4@196.021,12.509
NetNIXIE6_5: NIXIE6.5 Q66.3 | length 3
  Top Layer w0.508: Q66.3@197.858,8.31 NIXIE6.5@198.564,11.174
NetNIXIE6_6: NIXIE6.6 Q67.3 | length 3
  Top Layer w0.508: NIXIE6.6@201.436,11.174 Q67.3@202.142,8.31
NetNIXIE6_7: NIXIE6.7 Q68.3 | length 3
  Top Layer w0.508: NIXIE6.7@203.979,12.509 Q68.3@205.935,10.301
NetNIXIE6_8: NIXIE6.8 Q69.3 | length 3
  Top Layer w0.508: NIXIE6.8@205.61,14.872 Q69.3@208.368,13.826
NetNIXIE6_9: NIXIE6.9 Q70.3 | length 3
  Top Layer w0.508: NIXIE6.9@205.956,17.723 Q70.3@208.885,18.078
NetNIXIE6_A: NIXIE6.A R601.2 | length 4.2
  Top Layer w0.508: NIXIE6.A@200,23 R601.2@200,27.159
NetNIXIE6_LP: NIXIE6.LP Q61.3 | length 3
  Top Layer w0.508: Q61.3@195.841,24.925 NIXIE6.LP@197.212,22.313
NetNIXIE6_RP: NIXIE6.RP Q72.3 | length 3
  Top Layer w0.508: NIXIE6.RP@202.789,22.313 Q72.3@204.16,24.925
NetNIXIE7_0: NIXIE7.0 Q83.3 | length 3
  Top Layer w0.508: NIXIE7.0@239.938,20.408 Q83.3@242.366,22.084
NetNIXIE7_1: NIXIE7.1 Q74.3 | length 3
  Top Layer w0.508: Q74.3@227.634,22.084 NIXIE7.1@230.062,20.408
NetNIXIE7_2: NIXIE7.2 Q75.3 | length 3
  Top Layer w0.508: Q75.3@226.115,18.079 NIXIE7.2@229.044,17.723
NetNIXIE7_3: NIXIE7.3 Q76.3 | length 3
  Top Layer w0.508: Q76.3@226.632,13.826 NIXIE7.3@229.39,14.872
NetNIXIE7_4: NIXIE7.4 Q77.3 | length 3
  Top Layer w0.508: Q77.3@229.065,10.301 NIXIE7.4@231.021,12.509
NetNIXIE7_5: NIXIE7.5 Q78.3 | length 3
  Top Layer w0.508: Q78.3@232.858,8.31 NIXIE7.5@233.564,11.174
NetNIXIE7_6: NIXIE7.6 Q79.3 | length 3
  Top Layer w0.508: NIXIE7.6@236.436,11.174 Q79.3@237.142,8.31
NetNIXIE7_7: NIXIE7.7 Q80.3 | length 3
  Top Layer w0.508: NIXIE7.7@238.979,12.509 Q80.3@240.935,10.301
NetNIXIE7_8: NIXIE7.8 Q81.3 | length 3
  Top Layer w0.508: NIXIE7.8@240.61,14.872 Q81.3@243.368,13.826
NetNIXIE7_9: NIXIE7.9 Q82.3 | length 3
  Top Layer w0.508: NIXIE7.9@240.956,17.723 Q82.3@243.885,18.078
NetNIXIE7_A: NIXIE7.A R701.2 | length 4.2
  Top Layer w0.508: NIXIE7.A@235,23 R701.2@235,27.159
NetNIXIE7_LP: NIXIE7.LP Q73.3 | length 3
  Top Layer w0.508: Q73.3@230.841,24.925 NIXIE7.LP@232.212,22.313
NetNIXIE7_RP: NIXIE7.RP Q84.3 | length 2.9
  Top Layer w0.508: NIXIE7.RP@237.789,22.313 Q84.3@239.16,24.925
NetNIXIE8_0: NIXIE8.0 Q95.3 | length 3
  Top Layer w0.508: NIXIE8.0@274.938,20.408 Q95.3@277.366,22.084
NetNIXIE8_1: NIXIE8.1 Q86.3 | length 3
  Top Layer w0.508: Q86.3@262.634,22.084 NIXIE8.1@265.062,20.408
NetNIXIE8_2: NIXIE8.2 Q87.3 | length 3
  Top Layer w0.508: Q87.3@261.115,18.079 NIXIE8.2@264.044,17.723
NetNIXIE8_3: NIXIE8.3 Q88.3 | length 3
  Top Layer w0.508: Q88.3@261.632,13.826 NIXIE8.3@264.39,14.872
NetNIXIE8_4: NIXIE8.4 Q89.3 | length 3
  Top Layer w0.508: Q89.3@264.065,10.301 NIXIE8.4@266.021,12.509
NetNIXIE8_5: NIXIE8.5 Q90.3 | length 3
  Top Layer w0.508: Q90.3@267.858,8.31 NIXIE8.5@268.564,11.174
NetNIXIE8_6: NIXIE8.6 Q91.3 | length 3
  Top Layer w0.508: NIXIE8.6@271.436,11.174 Q91.3@272.142,8.31
NetNIXIE8_7: NIXIE8.7 Q92.3 | length 3
  Top Layer w0.508: NIXIE8.7@273.979,12.509 Q92.3@275.935,10.301
NetNIXIE8_8: NIXIE8.8 Q93.3 | length 3
  Top Layer w0.508: NIXIE8.8@275.61,14.872 Q93.3@278.368,13.826
NetNIXIE8_9: NIXIE8.9 Q94.3 | length 3
  Top Layer w0.508: NIXIE8.9@275.956,17.723 Q94.3@278.885,18.078
NetNIXIE8_A: NIXIE8.A R801.2 | length 4.2
  Top Layer w0.508: NIXIE8.A@270,23 R801.2@270,27.159
NetNIXIE8_LP: NIXIE8.LP Q85.3 | length 3
  Top Layer w0.508: Q85.3@265.841,24.925 NIXIE8.LP@267.212,22.313
NetNIXIE8_RP: NIXIE8.RP Q96.3 | length 3
  Top Layer w0.508: NIXIE8.RP@272.789,22.313 Q96.3@274.16,24.925
NetQ1_1: Q1.1 R1.1 | length 3.1
  Top Layer w0.508: R1.1@20.125,30.252 Q1.1@20.75,27.249
NetQ2_1: Q2.1 R2.1 | length 3.1
  Top Layer w0.508: R2.1@14.524,26.469 Q2.1@16.474,24.1
NetQ3_1: Q3.1 R3.1 | length 3.1
  Top Layer w0.508: R3.1@11.324,20.516 Q3.1@14.151,19.325
NetQ4_1: Q4.1 R4.1 | length 3.1
  Top Layer w0.508: R4.1@11.257,13.758 Q4.1@14.313,14.017
NetQ5_1: Q5.1 R5.1 | length 3.1
  Top Layer w0.508: R5.1@14.338,7.742 Q5.1@16.924,9.392
NetQ6_1: Q6.1 R6.1 | length 3.1
  Top Layer w0.508: R6.1@19.861,3.848 Q6.1@21.384,6.511
NetQ7_1: Q7.1 R7.1 | length 3.1
  Top Layer w0.508: R7.1@26.562,2.966 Q7.1@26.673,6.032
NetQ8_1: Q8.1 R8.1 | length 3.1
  Top Layer w0.508: Q8.1@31.579,8.066 R8.1@32.905,5.299
NetQ9_1: Q9.1 R9.1 | length 3.1
  Top Layer w0.508: Q9.1@34.977,12.146 R9.1@37.437,10.313
NetQ10_1: Q10.1 R10.1 | length 3.1
  Top Layer w0.508: Q10.1@36.09,17.339 R10.1@39.12,16.859
NetQ11_1: Q11.1 R11.1 | length 3.1
  Top Layer w0.508: Q11.1@34.662,22.454 R11.1@37.568,23.437
NetQ12_1: Q12.1 R12.1 | length 3.1
  Top Layer w0.508: Q12.1@31.021,26.319 R12.1@33.137,28.54
NetQ13_1: Q13.1 R13.1 | length 3.1
  Top Layer w0.508: R13.1@55.127,30.247 Q13.1@55.75,27.249
NetQ14_1: Q14.1 R14.1 | length 3.1
  Top Layer w0.508: R14.1@49.524,26.469 Q14.1@51.474,24.1
NetQ15_1: Q15.1 R15.1 | length 3.1
  Top Layer w0.508: R15.1@46.324,20.516 Q15.1@49.151,19.325
NetQ16_1: Q16.1 R16.1 | length 3.1
  Top Layer w0.508: R16.1@46.257,13.758 Q16.1@49.313,14.017
NetQ17_1: Q17.1 R17.1 | length 3.1
  Top Layer w0.508: R17.1@49.338,7.742 Q17.1@51.924,9.392
NetQ18_1: Q18.1 R18.1 | length 3.1
  Top Layer w0.508: R18.1@54.861,3.848 Q18.1@56.384,6.511
NetQ19_1: Q19.1 R19.1 | length 3.1
  Top Layer w0.508: R19.1@61.562,2.966 Q19.1@61.673,6.032
NetQ20_1: Q20.1 R20.1 | length 3.1
  Top Layer w0.508: Q20.1@66.579,8.066 R20.1@67.905,5.299
NetQ21_1: Q21.1 R21.1 | length 3.1
  Top Layer w0.508: Q21.1@69.977,12.146 R21.1@72.437,10.313
NetQ22_1: Q22.1 R22.1 | length 3.1
  Top Layer w0.508: Q22.1@71.09,17.339 R22.1@74.12,16.859
NetQ23_1: Q23.1 R23.1 | length 3.1
  Top Layer w0.508: Q23.1@69.662,22.454 R23.1@72.568,23.437
NetQ24_1: Q24.1 R24.1 | length 3.1
  Top Layer w0.508: Q24.1@66.021,26.319 R24.1@68.137,28.54
NetQ25_1: Q25.1 R25.1 | length 3.1
  Top Layer w0.508: R25.1@90.125,30.252 Q25.1@90.75,27.249
NetQ26_1: Q26.1 R26.1 | length 3.1
  Top Layer w0.508: R26.1@84.524,26.469 Q26.1@86.474,24.1
NetQ27_1: Q27.1 R27.1 | length 3.1
  Top Layer w0.508: R27.1@81.324,20.516 Q27.1@84.151,19.325
NetQ28_1: Q28.1 R28.1 | length 3.1
  Top Layer w0.508: R28.1@81.257,13.758 Q28.1@84.313,14.017
NetQ29_1: Q29.1 R29.1 | length 3.1
  Top Layer w0.508: R29.1@84.338,7.742 Q29.1@86.924,9.392
NetQ30_1: Q30.1 R30.1 | length 3.1
  Top Layer w0.508: R30.1@89.861,3.848 Q30.1@91.384,6.511
NetQ31_1: Q31.1 R31.1 | length 3.1
  Top Layer w0.508: R31.1@96.562,2.966 Q31.1@96.673,6.032
NetQ32_1: Q32.1 R32.1 | length 3.1
  Top Layer w0.508: Q32.1@101.579,8.066 R32.1@102.905,5.299
NetQ33_1: Q33.1 R33.1 | length 3.1
  Top Layer w0.508: Q33.1@104.977,12.146 R33.1@107.437,10.313
NetQ34_1: Q34.1 R34.1 | length 3.1
  Top Layer w0.508: Q34.1@106.09,17.339 R34.1@109.12,16.859
NetQ35_1: Q35.1 R35.1 | length 3.1
  Top Layer w0.508: Q35.1@104.662,22.454 R35.1@107.568,23.437
NetQ36_1: Q36.1 R36.1 | length 3.1
  Top Layer w0.508: Q36.1@101.021,26.319 R36.1@103.137,28.54
NetQ37_1: Q37.1 R37.1 | length 3.1
  Top Layer w0.508: R37.1@125.125,30.252 Q37.1@125.75,27.249
NetQ38_1: Q38.1 R38.1 | length 3.1
  Top Layer w0.508: R38.1@119.524,26.469 Q38.1@121.474,24.1
NetQ39_1: Q39.1 R39.1 | length 3.1
  Top Layer w0.508: R39.1@116.324,20.516 Q39.1@119.151,19.325
NetQ40_1: Q40.1 R40.1 | length 3.1
  Top Layer w0.508: R40.1@116.257,13.758 Q40.1@119.313,14.017
NetQ41_1: Q41.1 R41.1 | length 3.1
  Top Layer w0.508: R41.1@119.338,7.742 Q41.1@121.924,9.392
NetQ42_1: Q42.1 R42.1 | length 3.1
  Top Layer w0.508: R42.1@124.861,3.848 Q42.1@126.384,6.511
NetQ43_1: Q43.1 R43.1 | length 3.1
  Top Layer w0.508: R43.1@131.562,2.966 Q43.1@131.673,6.032
NetQ44_1: Q44.1 R44.1 | length 3.1
  Top Layer w0.508: Q44.1@136.579,8.066 R44.1@137.905,5.299
NetQ45_1: Q45.1 R45.1 | length 3.1
  Top Layer w0.508: Q45.1@139.977,12.146 R45.1@142.437,10.313
NetQ46_1: Q46.1 R46.1 | length 3.1
  Top Layer w0.508: Q46.1@141.09,17.339 R46.1@144.12,16.859
NetQ47_1: Q47.1 R47.1 | length 3.1
  Top Layer w0.508: Q47.1@139.662,22.454 R47.1@142.568,23.437
NetQ48_1: Q48.1 R48.1 | length 3.1
  Top Layer w0.508: Q48.1@136.021,26.319 R48.1@138.137,28.54
NetQ49_1: Q49.1 R49.1 | length 3.1
  Top Layer w0.508: R49.1@160.125,30.252 Q49.1@160.75,27.249
NetQ50_1: Q50.1 R50.1 | length 3.1
  Top Layer w0.508: R50.1@154.524,26.469 Q50.1@156.474,24.1
NetQ51_1: Q51.1 R51.1 | length 3.3
  Top Layer w0.508: R51.1@151.075,20.617 Q51.1@154.151,19.325
NetQ52_1: Q52.1 R52.1 | length 3.1
  Top Layer w0.508: R52.1@151.257,13.758 Q52.1@154.313,14.017
NetQ53_1: Q53.1 R53.1 | length 3.1
  Top Layer w0.508: R53.1@154.338,7.742 Q53.1@156.924,9.392
NetQ54_1: Q54.1 R54.1 | length 3.1
  Top Layer w0.508: R54.1@159.861,3.848 Q54.1@161.384,6.511
NetQ55_1: Q55.1 R55.1 | length 3.1
  Top Layer w0.508: R55.1@166.562,2.966 Q55.1@166.673,6.032
NetQ56_1: Q56.1 R56.1 | length 3.1
  Top Layer w0.508: Q56.1@171.579,8.066 R56.1@172.905,5.299
NetQ57_1: Q57.1 R57.1 | length 3.1
  Top Layer w0.508: Q57.1@174.977,12.146 R57.1@177.437,10.313
NetQ58_1: Q58.1 R58.1 | length 3.1
  Top Layer w0.508: Q58.1@176.09,17.339 R58.1@179.12,16.859
NetQ59_1: Q59.1 R59.1 | length 3.1
  Top Layer w0.508: Q59.1@174.662,22.454 R59.1@177.568,23.437
NetQ60_1: Q60.1 R60.1 | length 3.1
  Top Layer w0.508: Q60.1@171.021,26.319 R60.1@173.137,28.54
NetQ61_1: Q61.1 R61.1 | length 3.1
  Top Layer w0.508: R61.1@195.125,30.252 Q61.1@195.75,27.249
NetQ62_1: Q62.1 R62.1 | length 3.1
  Top Layer w0.508: R62.1@189.524,26.469 Q62.1@191.474,24.1
NetQ63_1: Q63.1 R63.1 | length 3.1
  Top Layer w0.508: R63.1@186.324,20.516 Q63.1@189.151,19.325
NetQ64_1: Q64.1 R64.1 | length 3.1
  Top Layer w0.508: R64.1@186.257,13.758 Q64.1@189.313,14.017
NetQ65_1: Q65.1 R65.1 | length 3.1
  Top Layer w0.508: R65.1@189.338,7.742 Q65.1@191.924,9.392
NetQ66_1: Q66.1 R66.1 | length 3.1
  Top Layer w0.508: R66.1@194.861,3.848 Q66.1@196.384,6.511
NetQ67_1: Q67.1 R67.1 | length 3.1
  Top Layer w0.508: R67.1@201.562,2.966 Q67.1@201.673,6.032
NetQ68_1: Q68.1 R68.1 | length 3.1
  Top Layer w0.508: Q68.1@206.579,8.066 R68.1@207.905,5.299
NetQ69_1: Q69.1 R69.1 | length 3.1
  Top Layer w0.508: Q69.1@209.977,12.146 R69.1@212.437,10.313
NetQ70_1: Q70.1 R70.1 | length 3.1
  Top Layer w0.508: Q70.1@211.09,17.339 R70.1@214.12,16.859
NetQ71_1: Q71.1 R71.1 | length 3.1
  Top Layer w0.508: Q71.1@209.662,22.454 R71.1@212.568,23.437
NetQ72_1: Q72.1 R72.1 | length 3.1
  Top Layer w0.508: Q72.1@206.021,26.319 R72.1@208.137,28.54
NetQ73_1: Q73.1 R73.1 | length 3.1
  Top Layer w0.508: R73.1@230.125,30.252 Q73.1@230.75,27.249
NetQ74_1: Q74.1 R74.1 | length 3.1
  Top Layer w0.508: R74.1@224.524,26.469 Q74.1@226.474,24.1
NetQ75_1: Q75.1 R75.1 | length 3.1
  Top Layer w0.508: R75.1@221.324,20.516 Q75.1@224.151,19.325
NetQ76_1: Q76.1 R76.1 | length 3.1
  Top Layer w0.508: R76.1@221.257,13.758 Q76.1@224.313,14.017
NetQ77_1: Q77.1 R77.1 | length 3.1
  Top Layer w0.508: R77.1@224.338,7.742 Q77.1@226.924,9.392
NetQ78_1: Q78.1 R78.1 | length 3.1
  Top Layer w0.508: R78.1@229.861,3.848 Q78.1@231.384,6.511
NetQ79_1: Q79.1 R79.1 | length 3.1
  Top Layer w0.508: R79.1@236.562,2.966 Q79.1@236.673,6.032
NetQ80_1: Q80.1 R80.1 | length 3.1
  Top Layer w0.508: Q80.1@241.579,8.066 R80.1@242.905,5.299
NetQ81_1: Q81.1 R81.1 | length 3.1
  Top Layer w0.508: Q81.1@244.977,12.146 R81.1@247.437,10.313
NetQ82_1: Q82.1 R82.1 | length 3.1
  Top Layer w0.508: Q82.1@246.09,17.339 R82.1@249.12,16.859
NetQ83_1: Q83.1 R83.1 | length 3.1
  Top Layer w0.508: Q83.1@244.662,22.454 R83.1@247.568,23.437
NetQ84_1: Q84.1 R84.1 | length 3.1
  Top Layer w0.508: Q84.1@241.021,26.319 R84.1@243.137,28.54
NetQ85_1: Q85.1 R85.1 | length 3.1
  Top Layer w0.508: R85.1@265.125,30.252 Q85.1@265.75,27.249
NetQ86_1: Q86.1 R86.1 | length 3.1
  Top Layer w0.508: R86.1@259.524,26.469 Q86.1@261.474,24.1
NetQ87_1: Q87.1 R87.1 | length 3.1
  Top Layer w0.508: R87.1@256.324,20.516 Q87.1@259.151,19.325
NetQ88_1: Q88.1 R88.1 | length 3.1
  Top Layer w0.508: R88.1@256.257,13.758 Q88.1@259.313,14.017
NetQ89_1: Q89.1 R89.1 | length 3.1
  Top Layer w0.508: R89.1@259.338,7.742 Q89.1@261.924,9.392
NetQ90_1: Q90.1 R90.1 | length 3.1
  Top Layer w0.508: R90.1@264.861,3.848 Q90.1@266.384,6.511
NetQ91_1: Q91.1 R91.1 | length 3.1
  Top Layer w0.508: R91.1@271.562,2.966 Q91.1@271.673,6.032
NetQ92_1: Q92.1 R92.1 | length 3.1
  Top Layer w0.508: Q92.1@276.579,8.066 R92.1@277.905,5.299
NetQ93_1: Q93.1 R93.1 | length 3.1
  Top Layer w0.508: Q93.1@279.977,12.146 R93.1@282.437,10.313
NetQ94_1: Q94.1 R94.1 | length 3.1
  Top Layer w0.508: Q94.1@281.09,17.339 R94.1@284.12,16.859
NetQ95_1: Q95.1 R95.1 | length 3.1
  Top Layer w0.508: Q95.1@279.662,22.454 R95.1@282.568,23.437
NetQ96_1: Q96.1 R96.1 | length 3.1
  Top Layer w0.508: Q96.1@276.021,26.319 R96.1@278.137,28.54
NetQ100_1: pad.100 Q100.1 U1.15 | length 54.4
  Top Layer w0.254: pad.100@25,58 pad.100@25,62 25,64 28.175,67.175 U1.15@28.175,82
  Top Layer w0.508: v1(27.65,32) Q100.1@27.65,33.95
  Bottom Layer w0.254: pad.100@25,58 25,34.65 v1(27.65,32)
NetQ100_2: Q100.2 R100.1 | length 1.9
  Top Layer w0.508: Q100.2@29.65,33.95 R100.1@31.55,33.954
NetQ100_3: Q100.3 Q101.1 R102.2 | length 4.7
  Top Layer w0.508: Q101.1@26,36.05 Q100.3@28.65,36.05 R102.2@28.651,38.1
NetQ101_3: Q101.3 R101.1 | length 3.1
  Top Layer w0.508: R101.1@25,30.842 Q101.3@25,33.95
NetQ200_1: pad.200 Q200.1 U2.5 | length 84.4
  Top Layer w0.254: U2.5@44.782,88 v1(44.782,93) ; v1(50,79) 50,73.31 60,63.31 pad.200@60,62 pad.200@60,58
  Top Layer w0.508: v1(62.65,32) Q200.1@62.65,33.95
  Bottom Layer w0.254: v1(44.782,93) 46.106,94.324 51.536,94.324 53.944,91.916 53.944,85.944 50,82 v1(50,79) ; pad.200@60,58 60,34.65 v1(62.65,32)
NetQ200_2: Q200.2 R200.1 | length 1.9
  Top Layer w0.508: Q200.2@64.65,33.95 R200.1@66.55,33.954
NetQ200_3: Q200.3 Q201.1 R202.2 | length 4.7
  Top Layer w0.508: Q201.1@61,36.05 Q200.3@63.65,36.05 R202.2@63.652,38.1
NetQ201_3: Q201.3 R201.1 | length 3.1
  Top Layer w0.508: R201.1@60,30.842 Q201.3@60,33.95
NetQ300_1: pad.300 Q300.1 U4.2 | length 70.7
  Top Layer w0.254: U4.2@89.425,88 v1(89.425,91) ; pad.300@95,58 pad.300@95,62 95,64 99,68 v1(99,79)
  Top Layer w0.508: v1(97.65,32) Q300.1@97.65,33.95
  Bottom Layer w0.254: v1(89.425,91) 89.425,88.575 v1(99,79) ; pad.300@95,58 95,34.65 v1(97.65,32)
NetQ300_2: Q300.2 R300.1 | length 1.9
  Top Layer w0.508: Q300.2@99.65,33.95 R300.1@101.55,33.954
NetQ300_3: Q300.3 Q301.1 R302.2 | length 4.7
  Top Layer w0.508: Q301.1@96,36.05 Q300.3@98.65,36.05 R302.2@98.651,38.1
NetQ301_3: Q301.3 R301.1 | length 3.1
  Top Layer w0.508: R301.1@95,30.842 Q301.3@95,33.95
